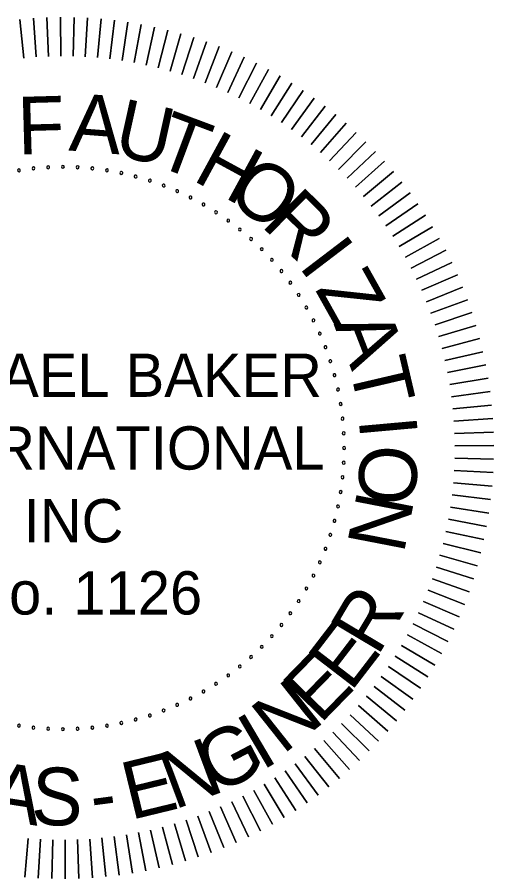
# Model space of a CAD drawing. Extents: x 185 to 5012, y 113 to 2127.
# Drawn here: x 2771.5 to 2909.1, y 178.5 to 427.4 of the extents above; entities that cross this region are included whole.
import ezdxf

# ---------------------------------------------------------------- set-up
doc = ezdxf.new("R2010")
doc.units = 0
doc.layers.add('STAMP_BOL', color=7, linetype='Continuous')

msp = doc.modelspace()

# ---------------------------------------------------------------- linework, layer by layer
at = {"layer": 'STAMP_BOL'}
for points in [[(2773.38, 415.59), (2772.26, 426.75)], [(2772.26, 426.75), (2773.38, 415.59)], [(2776.92, 415.89), (2776.15, 427.08)], [(2776.15, 427.08), (2776.92, 415.89)], [(2780.47, 416.07), (2780.06, 427.29)], [(2780.06, 427.29), (2780.47, 416.07)], [(2784.03, 416.15), (2783.97, 427.37)], [(2783.97, 427.37), (2784.03, 416.15)], [(2787.59, 416.11), (2787.88, 427.33)], [(2787.88, 427.33), (2787.59, 416.11)], [(2791.14, 415.97), (2791.78, 427.17)], [(2791.78, 427.17), (2791.14, 415.97)], [(2794.69, 415.71), (2795.68, 426.88)], [(2795.68, 426.88), (2794.69, 415.71)], [(2798.22, 415.34), (2799.57, 426.48)], [(2799.57, 426.48), (2798.22, 415.34)], [(2801.75, 414.85), (2803.44, 425.95)], [(2803.44, 425.95), (2801.75, 414.85)], [(2805.25, 414.26), (2807.3, 425.3)], [(2807.3, 425.3), (2805.25, 414.26)], [(2808.74, 413.56), (2811.13, 424.53)], [(2811.13, 424.53), (2808.74, 413.56)], [(2812.2, 412.75), (2814.93, 423.63)], [(2814.93, 423.63), (2812.2, 412.75)], [(2815.64, 411.83), (2818.71, 422.62)], [(2818.71, 422.62), (2815.64, 411.83)], [(2819.05, 410.8), (2822.45, 421.5)], [(2822.45, 421.5), (2819.05, 410.8)], [(2822.42, 409.67), (2826.16, 420.25)], [(2826.16, 420.25), (2822.42, 409.67)], [(2825.75, 408.43), (2829.82, 418.89)], [(2829.82, 418.89), (2825.75, 408.43)], [(2829.04, 407.09), (2833.44, 417.41)], [(2833.44, 417.41), (2829.04, 407.09)], [(2832.29, 405.64), (2837.02, 415.82)], [(2837.02, 415.82), (2832.29, 405.64)], [(2835.5, 404.1), (2840.54, 414.12)], [(2840.54, 414.12), (2835.5, 404.1)], [(2838.65, 402.45), (2844, 412.31)], [(2844, 412.31), (2838.65, 402.45)], [(2841.75, 400.7), (2847.41, 410.4)], [(2847.41, 410.4), (2841.75, 400.7)], [(2844.79, 398.86), (2850.75, 408.37)], [(2850.75, 408.37), (2844.79, 398.86)], [(2847.77, 396.93), (2854.03, 406.24)], [(2854.03, 406.24), (2847.77, 396.93)], [(2850.7, 394.9), (2857.24, 404.01)], [(2857.24, 404.01), (2850.7, 394.9)], [(2853.55, 392.78), (2860.38, 401.68)], [(2860.38, 401.68), (2853.55, 392.78)], [(2856.34, 390.57), (2863.45, 399.26)], [(2863.45, 399.26), (2856.34, 390.57)], [(2859.06, 388.27), (2866.43, 396.73)], [(2866.43, 396.73), (2859.06, 388.27)], [(2869.34, 394.12), (2861.7, 385.9)], [(2861.7, 385.9), (2869.34, 394.12)], [(2872.16, 391.41), (2864.27, 383.43)], [(2864.27, 383.43), (2872.16, 391.41)], [(2874.9, 388.62), (2866.76, 380.89)], [(2866.76, 380.89), (2874.9, 388.62)], [(2877.54, 385.75), (2869.17, 378.28)], [(2869.17, 378.28), (2877.54, 385.75)], [(2880.1, 382.79), (2871.49, 375.59)], [(2871.49, 375.59), (2880.1, 382.79)], [(2882.56, 379.75), (2873.73, 372.82)], [(2873.73, 372.82), (2882.56, 379.75)], [(2884.93, 376.64), (2875.88, 369.99)], [(2875.88, 369.99), (2884.93, 376.64)], [(2887.19, 373.45), (2877.94, 367.09)], [(2877.94, 367.09), (2887.19, 373.45)], [(2889.36, 370.2), (2879.91, 364.13)], [(2879.91, 364.13), (2889.36, 370.2)], [(2891.42, 366.87), (2881.79, 361.11)], [(2881.79, 361.11), (2891.42, 366.87)], [(2893.37, 363.49), (2883.57, 358.03)], [(2883.57, 358.03), (2893.37, 363.49)], [(2895.22, 360.04), (2885.25, 354.89)], [(2885.25, 354.89), (2895.22, 360.04)], [(2896.96, 356.54), (2886.83, 351.71)], [(2886.83, 351.71), (2896.96, 356.54)], [(2898.59, 352.99), (2888.31, 348.48)], [(2888.31, 348.48), (2898.59, 352.99)], [(2900.1, 349.39), (2889.69, 345.2)], [(2889.69, 345.2), (2900.1, 349.39)], [(2901.51, 345.74), (2890.97, 341.88)], [(2890.97, 341.88), (2901.51, 345.74)], [(2902.79, 342.05), (2892.14, 338.52)], [(2892.14, 338.52), (2902.79, 342.05)], [(2903.96, 338.32), (2893.2, 335.12)], [(2893.2, 335.12), (2903.96, 338.32)], [(2905.02, 334.55), (2894.16, 331.7)], [(2894.16, 331.7), (2905.02, 334.55)], [(2905.95, 330.75), (2895.01, 328.25)], [(2895.01, 328.25), (2905.95, 330.75)], [(2906.76, 326.93), (2895.75, 324.77)], [(2895.75, 324.77), (2906.76, 326.93)], [(2907.46, 323.08), (2896.38, 321.27)], [(2896.38, 321.27), (2907.46, 323.08)], [(2908.03, 319.22), (2896.9, 317.75)], [(2896.9, 317.75), (2908.03, 319.22)], [(2908.48, 315.33), (2897.31, 314.22)], [(2897.31, 314.22), (2908.48, 315.33)], [(2908.81, 311.44), (2897.61, 310.67)], [(2897.61, 310.67), (2908.81, 311.44)], [(2909.02, 307.53), (2897.8, 307.12)], [(2897.8, 307.12), (2909.02, 307.53)], [(2909.1, 303.63), (2897.88, 303.56)], [(2897.88, 303.56), (2909.1, 303.63)], [(2909.06, 299.72), (2897.84, 300.01)], [(2897.84, 300.01), (2909.06, 299.72)], [(2908.9, 295.81), (2897.69, 296.45)], [(2897.69, 296.45), (2908.9, 295.81)], [(2908.61, 291.91), (2897.43, 292.91)], [(2897.43, 292.91), (2908.61, 291.91)], [(2908.2, 288.02), (2897.06, 289.37)], [(2897.06, 289.37), (2908.2, 288.02)], [(2907.68, 284.15), (2896.58, 285.84)], [(2896.58, 285.84), (2907.68, 284.15)], [(2907.02, 280.3), (2895.99, 282.34)], [(2895.99, 282.34), (2907.02, 280.3)], [(2906.25, 276.46), (2895.29, 278.85)], [(2895.29, 278.85), (2906.25, 276.46)], [(2905.36, 272.66), (2894.48, 275.39)], [(2894.48, 275.39), (2905.36, 272.66)], [(2904.35, 268.88), (2893.56, 271.95)], [(2893.56, 271.95), (2904.35, 268.88)], [(2903.22, 265.14), (2892.53, 268.55)], [(2892.53, 268.55), (2903.22, 265.14)], [(2901.98, 261.43), (2891.4, 265.18)], [(2891.4, 265.18), (2901.98, 261.43)], [(2900.62, 257.77), (2890.16, 261.84)], [(2890.16, 261.84), (2900.62, 257.77)], [(2899.14, 254.15), (2888.82, 258.55)], [(2888.82, 258.55), (2899.14, 254.15)], [(2897.55, 250.58), (2887.37, 255.3)], [(2887.37, 255.3), (2897.55, 250.58)], [(2895.85, 247.06), (2885.82, 252.1)], [(2885.82, 252.1), (2895.85, 247.06)], [(2894.04, 243.59), (2884.18, 248.94)], [(2884.18, 248.94), (2894.04, 243.59)], [(2892.12, 240.18), (2882.43, 245.84)], [(2882.43, 245.84), (2892.12, 240.18)], [(2890.1, 236.84), (2880.59, 242.8)], [(2880.59, 242.8), (2890.1, 236.84)], [(2887.97, 233.56), (2878.65, 239.82)], [(2878.65, 239.82), (2887.97, 233.56)], [(2885.74, 230.35), (2876.62, 236.9)], [(2876.62, 236.9), (2885.74, 230.35)], [(2883.41, 227.21), (2874.51, 234.04)], [(2874.51, 234.04), (2883.41, 227.21)], [(2880.98, 224.15), (2872.3, 231.25)], [(2872.3, 231.25), (2880.98, 224.15)], [(2878.46, 221.16), (2870, 228.53)], [(2870, 228.53), (2878.46, 221.16)], [(2875.85, 218.25), (2867.62, 225.89)], [(2867.62, 225.89), (2875.85, 218.25)], [(2873.14, 215.43), (2865.16, 223.32)], [(2865.16, 223.32), (2873.14, 215.43)], [(2870.35, 212.69), (2862.62, 220.83)], [(2862.62, 220.83), (2870.35, 212.69)], [(2867.47, 210.05), (2860, 218.42)], [(2860, 218.42), (2867.47, 210.05)], [(2864.51, 207.49), (2857.31, 216.1)], [(2857.31, 216.1), (2864.51, 207.49)], [(2858.36, 202.67), (2851.72, 211.71)], [(2851.72, 211.71), (2858.36, 202.67)], [(2861.48, 205.03), (2854.55, 213.86)], [(2854.55, 213.86), (2861.48, 205.03)], [(2855.18, 200.4), (2848.82, 209.65)], [(2848.82, 209.65), (2855.18, 200.4)], [(2851.92, 198.24), (2845.86, 207.68)], [(2845.86, 207.68), (2851.92, 198.24)], [(2848.6, 196.18), (2842.83, 205.8)], [(2842.83, 205.8), (2848.6, 196.18)], [(2841.77, 192.37), (2836.62, 202.34)], [(2836.62, 202.34), (2841.77, 192.37)], [(2845.22, 194.22), (2839.76, 204.02)], [(2839.76, 204.02), (2845.22, 194.22)], [(2834.72, 189), (2830.2, 199.28)], [(2830.2, 199.28), (2834.72, 189)], [(2838.27, 190.63), (2833.44, 200.76)], [(2833.44, 200.76), (2838.27, 190.63)], [(2827.46, 186.08), (2823.6, 196.62)], [(2823.6, 196.62), (2827.46, 186.08)], [(2831.11, 187.49), (2826.92, 197.9)], [(2826.92, 197.9), (2831.11, 187.49)], [(2820.04, 183.63), (2816.85, 194.39)], [(2816.85, 194.39), (2820.04, 183.63)], [(2823.77, 184.8), (2820.25, 195.45)], [(2820.25, 195.45), (2823.77, 184.8)], [(2808.66, 180.83), (2806.49, 191.84)], [(2806.49, 191.84), (2808.66, 180.83)], [(2812.48, 181.64), (2809.97, 192.58)], [(2809.97, 192.58), (2812.48, 181.64)], [(2816.28, 182.57), (2813.43, 193.43)], [(2813.43, 193.43), (2816.28, 182.57)], [(2773.64, 178.98), (2774.63, 190.16)], [(2774.63, 190.16), (2773.64, 178.98)], [(2777.54, 178.69), (2778.18, 189.9)], [(2778.18, 189.9), (2777.54, 178.69)], [(2781.44, 178.53), (2781.73, 189.75)], [(2781.73, 189.75), (2781.44, 178.53)], [(2785.35, 178.49), (2785.29, 189.72)], [(2785.29, 189.72), (2785.35, 178.49)], [(2789.26, 178.58), (2788.85, 189.79)], [(2788.85, 189.79), (2789.26, 178.58)], [(2793.17, 178.78), (2792.4, 189.98)], [(2792.4, 189.98), (2793.17, 178.78)], [(2797.06, 179.11), (2795.94, 190.28)], [(2795.94, 190.28), (2797.06, 179.11)], [(2800.94, 179.56), (2799.48, 190.69)], [(2799.48, 190.69), (2800.94, 179.56)], [(2804.81, 180.13), (2802.99, 191.21)], [(2802.99, 191.21), (2804.81, 180.13)]]:
    msp.add_lwpolyline(points, dxfattribs=at)
for centre, start, end in [((2771.95, 383.15), 9, 189), ((2776.17, 383.7), 6, 186), ((2776.17, 383.7), 186, 6), ((2780.41, 384.04), 3, 183), ((2780.41, 384.04), 183, 3), ((2784.66, 384.15), 0, 180), ((2784.66, 384.15), 180, 0), ((2788.91, 384.04), 357, 177), ((2788.91, 384.04), 177, 357), ((2793.15, 383.7), 354, 174), ((2793.15, 383.7), 174, 354), ((2797.36, 383.15), 351, 171), ((2771.95, 383.15), 189, 9), ((2797.36, 383.15), 171, 351), ((2801.54, 382.37), 168, 348), ((2801.54, 382.37), 348, 168), ((2805.68, 381.38), 165, 345), ((2805.68, 381.38), 345, 165), ((2809.76, 380.17), 162, 342), ((2809.76, 380.17), 342, 162), ((2813.76, 378.75), 159, 339), ((2813.76, 378.75), 339, 159), ((2817.69, 377.13), 156, 336), ((2817.69, 377.13), 336, 156), ((2821.53, 375.3), 153, 333), ((2821.53, 375.3), 333, 153), ((2825.27, 373.27), 150, 330), ((2825.27, 373.27), 330, 150), ((2828.89, 371.04), 147, 327), ((2828.89, 371.04), 327, 147), ((2832.4, 368.64), 144, 324), ((2832.4, 368.64), 324, 144), ((2835.77, 366.05), 141, 321), ((2835.77, 366.05), 321, 141), ((2839, 363.29), 138, 318), ((2839, 363.29), 318, 138), ((2842.09, 360.36), 135, 315), ((2842.09, 360.36), 315, 135), ((2845.01, 357.28), 132, 312), ((2845.01, 357.28), 312, 132), ((2847.78, 354.04), 129, 309), ((2847.78, 354.04), 309, 129), ((2850.36, 350.67), 126, 306), ((2850.36, 350.67), 306, 126), ((2852.77, 347.16), 123, 303), ((2852.77, 347.16), 303, 123), ((2854.99, 343.54), 120, 300), ((2854.99, 343.54), 300, 120), ((2857.02, 339.8), 117, 297), ((2857.02, 339.8), 297, 117), ((2858.85, 335.97), 114, 294), ((2858.85, 335.97), 294, 114), ((2860.48, 332.04), 111, 291), ((2860.48, 332.04), 291, 111), ((2861.9, 328.03), 108, 288), ((2861.9, 328.03), 288, 108), ((2863.11, 323.95), 105, 285), ((2863.11, 323.95), 285, 105), ((2864.1, 319.82), 102, 282), ((2864.1, 319.82), 282, 102), ((2864.87, 315.64), 99, 279), ((2864.87, 315.64), 279, 99), ((2865.43, 311.42), 96, 276), ((2865.43, 311.42), 276, 96), ((2865.76, 307.18), 93, 273), ((2865.76, 307.18), 273, 93), ((2865.87, 302.93), 90, 270), ((2865.87, 302.93), 270, 90), ((2865.76, 298.68), 87, 267), ((2865.76, 298.68), 267, 87), ((2865.43, 294.44), 84, 264), ((2865.43, 294.44), 264, 84), ((2864.87, 290.23), 81, 261), ((2864.87, 290.23), 261, 81), ((2864.1, 286.05), 78, 258), ((2864.1, 286.05), 258, 78), ((2863.11, 281.91), 75, 255), ((2863.11, 281.91), 255, 75), ((2861.9, 277.84), 72, 252), ((2861.9, 277.84), 252, 72), ((2860.48, 273.83), 69, 249), ((2860.48, 273.83), 249, 69), ((2858.85, 269.9), 66, 246), ((2858.85, 269.9), 246, 66), ((2857.02, 266.06), 63, 243), ((2857.02, 266.06), 243, 63), ((2854.99, 262.32), 60, 240), ((2854.99, 262.32), 240, 60), ((2852.77, 258.7), 57, 237), ((2852.77, 258.7), 237, 57), ((2850.36, 255.2), 54, 234), ((2850.36, 255.2), 234, 54), ((2847.78, 251.82), 51, 231), ((2847.78, 251.82), 231, 51), ((2845.01, 248.59), 48, 228), ((2845.01, 248.59), 228, 48), ((2842.09, 245.5), 45, 225), ((2842.09, 245.5), 225, 45), ((2839, 242.58), 42, 222), ((2839, 242.58), 222, 42), ((2835.77, 239.82), 39, 219), ((2835.77, 239.82), 219, 39), ((2832.4, 237.23), 36, 216), ((2832.4, 237.23), 216, 36), ((2828.89, 234.82), 33, 213), ((2828.89, 234.82), 213, 33), ((2825.27, 232.6), 30, 210), ((2825.27, 232.6), 210, 30), ((2817.69, 228.74), 24, 204), ((2821.53, 230.57), 27, 207), ((2821.53, 230.57), 207, 27), ((2813.76, 227.11), 21, 201), ((2813.76, 227.11), 201, 21), ((2817.69, 228.74), 204, 24), ((2805.68, 224.48), 15, 195), ((2805.68, 224.48), 195, 15), ((2809.76, 225.69), 18, 198), ((2809.76, 225.69), 198, 18), ((2771.95, 222.72), 351, 171), ((2771.95, 222.72), 171, 351), ((2776.17, 222.16), 174, 354), ((2776.17, 222.16), 354, 174), ((2780.41, 221.83), 357, 177), ((2780.41, 221.83), 177, 357), ((2784.66, 221.72), 0, 180), ((2784.66, 221.72), 180, 0), ((2788.91, 221.83), 3, 183), ((2788.91, 221.83), 183, 3), ((2793.15, 222.16), 6, 186), ((2793.15, 222.16), 186, 6), ((2797.36, 222.72), 9, 189), ((2797.36, 222.72), 189, 9), ((2801.54, 223.49), 12, 192), ((2801.54, 223.49), 192, 12)]:
    msp.add_arc(centre, 0.417, start, end, dxfattribs=at)

# ---------------------------------------------------------------- texts
for s, rotation, p in [('F', 1.5867, (2771.73, 387.67)), ('A', 355.5955, (2786.18, 388.89)), ('U', 347.5481, (2798.79, 387.7)), ('T', 339.5007, (2810.43, 384.92)), ('H', 331.4533, (2821.73, 380.46)), ('O', 323.4059, (2831.3, 375.19)), ('R', 315.3585, (2841.62, 367.29)), ('I', 307.3112, (2852.46, 355.55)), ('Z', 299.2638, (2857.35, 348.76)), ('A', 291.2164, (2862.82, 338.73)), ('T', 283.169, (2867.18, 326.94)), ('I', 275.1216, (2870.07, 311.34)), ('O', 267.0743, (2870.65, 304.18)), ('N', 259.0269, (2869.78, 291.07)), ('R', 59.2262, (2875.53, 242.49)), ('E', 52.4765, (2867.79, 232.23)), ('E', 45.7268, (2858.91, 222.95)), ('N', 38.4196, (2848.13, 214.16)), ('I', 30.5495, (2842.08, 209.57)), ('G', 27.7404, (2828.9, 202.57)), ('N', 20.4332, (2816.77, 198.36)), ('E', 13.6835, (2804.2, 195.42)), ('A', 351.1991, (2762.61, 196.05)), ('S', 357.9489, (2775.32, 194.2)), ('-', 7.5077, (2793.51, 194.16))]:
    msp.add_text(s, height=16.67, rotation=rotation, dxfattribs=at).set_placement(p)
for s, height, p in [('MICHAEL BAKER', 12.5016, (2723.83, 317.71)), (' INTERNATIONAL', 12.5016, (2721.82, 296.69)), ('INC', 12.502, (2773.34, 275.67)), (' No. 1126', 12.502, (2752.39, 254.83))]:
    msp.add_text(s, height=height, dxfattribs=at).set_placement(p)

doc.saveas('drawing.dxf')
